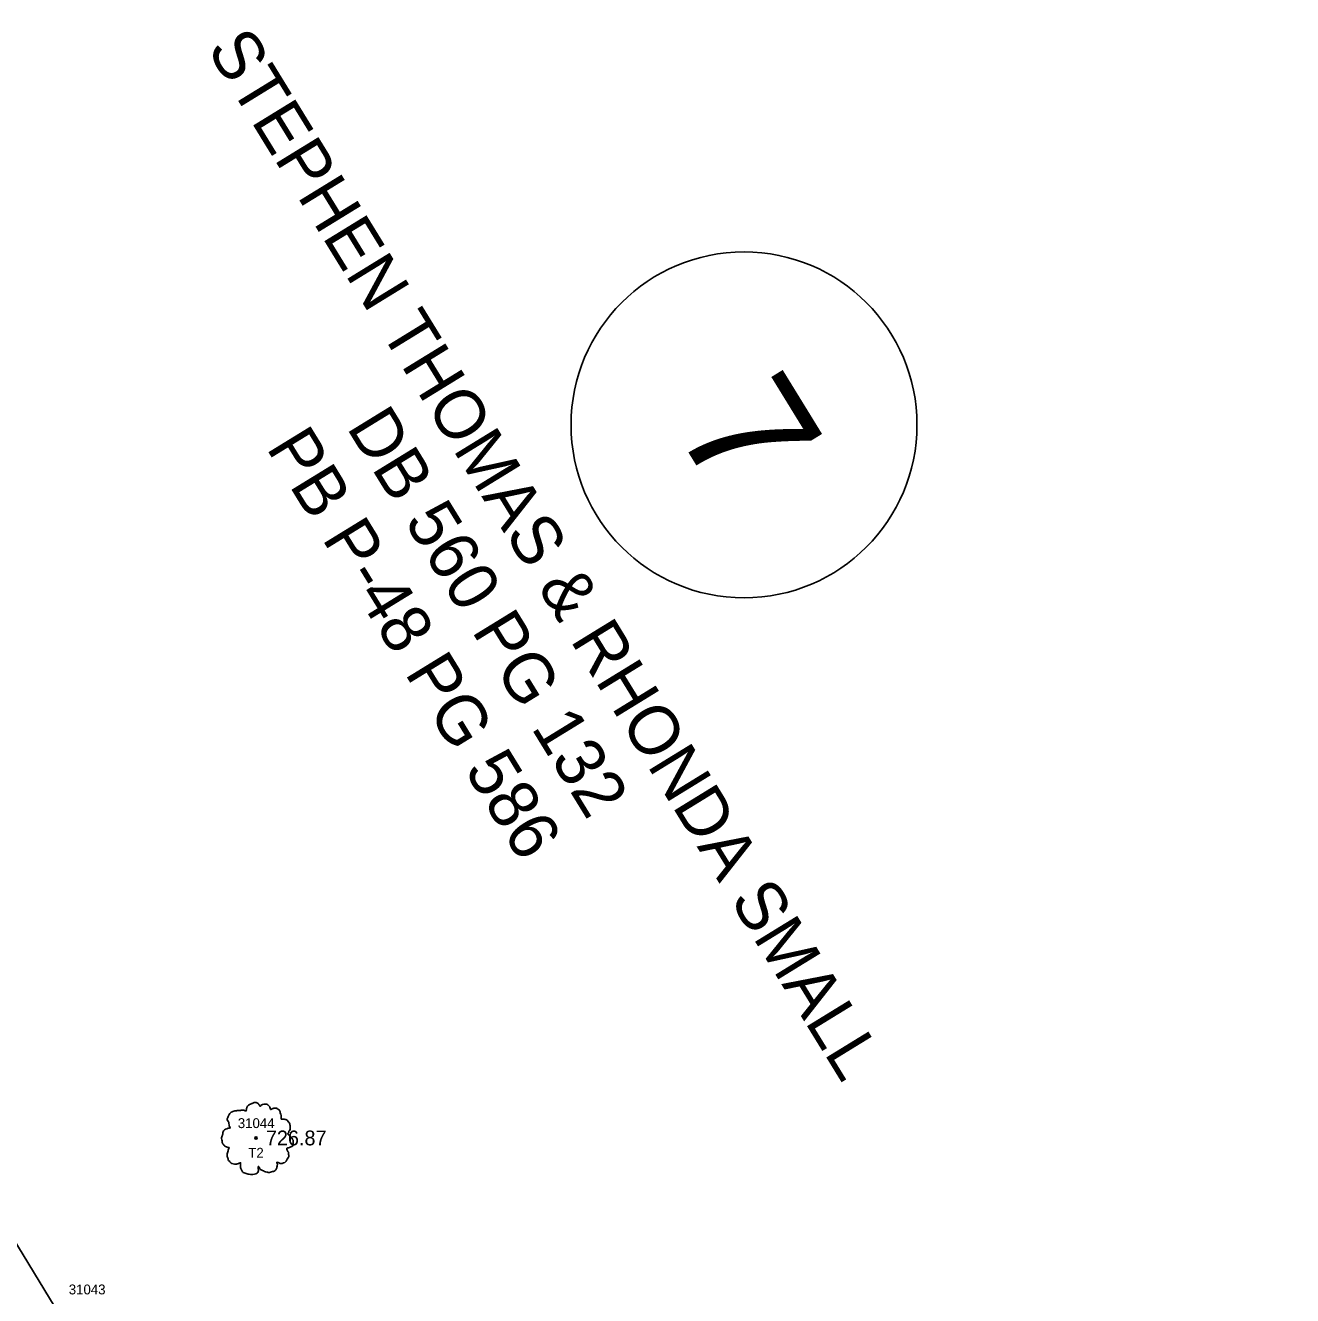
# Model space of a CAD drawing. Extents: x 1375131 to 1378678, y 999028 to 1004053.
# Drawn here: x 1377739.9 to 1377868.1, y 1001103.2 to 1001231.8 of the extents above; entities that cross this region are included whole.
import ezdxf

# ---------------------------------------------------------------- set-up
doc = ezdxf.new("R2010")
doc.units = 0
for name, color, linetype in [('RD_EX_DV_TX_Prop(Owner ID)', 7, 'Continuous'), ('RD_EX_Fence_Other_txCode', 7, 'Continuous'), ('RD_EX_RW', 7, 'Continuous'), ('RD_EX_TX_VEG_ELEV', 7, 'Continuous'), ('RD_EX_VEG', 7, 'Continuous'), ('RD_EX_VEG_txCode', 7, 'Continuous'), ('RD_SMD_Locator', 7, 'Continuous')]:
    doc.layers.add(name, color=color, linetype=linetype)

msp = doc.modelspace()

# ---------------------------------------------------------------- linework, layer by layer
at = {"layer": 'RD_EX_DV_TX_Prop(Owner ID)'}
msp.add_circle((1377812.64, 1001191.36), 17.5, dxfattribs=at)
at = {"layer": 'RD_EX_RW'}
msp.add_line((1377592.75, 1001348.44), (1377983.57, 1000707.36), dxfattribs=at)
at = {"layer": 'RD_EX_VEG'}
for centre, radius in [((1377763.27, 1001119.2), 0.125), ((1377763.26, 1001119.19), 0.00005)]:
    msp.add_circle(centre, radius, dxfattribs=at)
for points in [[(1377763.33, 1001122.78), (1377763.18, 1001122.8), (1377763.02, 1001122.75), (1377762.89, 1001122.7), (1377762.78, 1001122.66), (1377762.67, 1001122.61), (1377762.52, 1001122.52), (1377762.41, 1001122.42), (1377762.34, 1001122.3), (1377762.32, 1001122.18), (1377762.29, 1001122.05), (1377762.29, 1001121.96), (1377762.23, 1001121.95), (1377762.16, 1001121.96), (1377762.03, 1001122), (1377761.91, 1001122), (1377761.78, 1001122), (1377761.61, 1001121.98), (1377761.43, 1001121.98), (1377761.29, 1001121.96), (1377761.13, 1001121.93), (1377760.94, 1001121.87), (1377760.77, 1001121.81), (1377760.62, 1001121.68), (1377760.49, 1001121.45), (1377760.43, 1001121.27), (1377760.36, 1001121.15), (1377760.43, 1001120.92), (1377760.52, 1001120.75), (1377760.53, 1001120.65), (1377760.57, 1001120.43), (1377760.62, 1001120.32), (1377760.68, 1001120.22), (1377760.64, 1001120.21), (1377760.46, 1001120.18), (1377760.31, 1001120.13), (1377760.09, 1001120.02), (1377759.98, 1001119.91), (1377759.93, 1001119.75), (1377759.92, 1001119.57), (1377759.87, 1001119.47), (1377759.83, 1001119.33), (1377759.82, 1001119.3), (1377759.79, 1001119.13), (1377759.84, 1001118.91), (1377759.86, 1001118.73), (1377759.92, 1001118.62), (1377759.99, 1001118.53), (1377760.08, 1001118.41), (1377760.28, 1001118.3), (1377760.44, 1001118.25), (1377760.54, 1001118.23), (1377760.46, 1001117.98), (1377760.43, 1001117.81), (1377760.37, 1001117.61), (1377760.37, 1001117.57), (1377760.34, 1001117.34), (1377760.42, 1001117.17), (1377760.46, 1001116.99), (1377760.54, 1001116.87), (1377760.68, 1001116.72), (1377760.84, 1001116.61), (1377761.09, 1001116.55), (1377761.29, 1001116.56), (1377761.58, 1001116.65), (1377761.71, 1001116.69), (1377761.69, 1001116.6), (1377761.71, 1001116.41), (1377761.71, 1001116.2), (1377761.78, 1001116.04), (1377761.83, 1001115.9), (1377761.91, 1001115.77), (1377762.07, 1001115.66), (1377762.27, 1001115.62), (1377762.48, 1001115.55), (1377762.71, 1001115.51), (1377762.96, 1001115.5), (1377763.26, 1001115.57), (1377763.39, 1001115.64), (1377763.44, 1001115.72), (1377763.54, 1001115.91), (1377763.52, 1001116.02), (1377763.53, 1001116.32), (1377763.58, 1001116.24), (1377763.67, 1001116.06), (1377763.92, 1001115.91), (1377764.12, 1001115.82), (1377764.36, 1001115.75), (1377764.51, 1001115.71), (1377764.74, 1001115.75), (1377764.93, 1001115.79), (1377765.12, 1001115.85), (1377765.27, 1001115.99), (1377765.36, 1001116.12), (1377765.38, 1001116.26), (1377765.42, 1001116.45), (1377765.44, 1001116.54)], [(1377765.44, 1001116.54), (1377765.41, 1001116.62), (1377765.38, 1001116.75), (1377765.42, 1001116.74), (1377765.5, 1001116.71), (1377765.64, 1001116.65), (1377765.75, 1001116.61), (1377765.92, 1001116.62), (1377766.05, 1001116.67), (1377766.28, 1001116.81), (1377766.42, 1001117.05), (1377766.55, 1001117.25), (1377766.59, 1001117.41), (1377766.57, 1001117.52), (1377766.55, 1001117.77), (1377766.45, 1001117.9), (1377766.43, 1001117.96), (1377766.38, 1001118.16), (1377766.42, 1001118.18), (1377766.55, 1001118.21), (1377766.74, 1001118.27), (1377766.88, 1001118.33), (1377766.99, 1001118.42), (1377767.03, 1001118.53), (1377767.02, 1001118.73), (1377767.04, 1001118.93), (1377767, 1001119.01), (1377766.95, 1001119.08), (1377766.92, 1001119.18), (1377766.84, 1001119.26), (1377766.79, 1001119.33), (1377766.74, 1001119.38), (1377766.68, 1001119.46), (1377766.59, 1001119.52), (1377766.52, 1001119.55), (1377766.49, 1001119.62), (1377766.57, 1001119.72), (1377766.59, 1001119.77), (1377766.6, 1001119.88), (1377766.72, 1001120.06), (1377766.74, 1001120.26), (1377766.72, 1001120.47), (1377766.69, 1001120.61), (1377766.62, 1001120.75), (1377766.52, 1001120.87), (1377766.45, 1001120.96), (1377766.37, 1001121.02), (1377766.2, 1001121.08), (1377766.08, 1001121.11), (1377765.9, 1001121.11), (1377765.8, 1001121.13), (1377765.82, 1001121.16), (1377765.82, 1001121.23), (1377765.82, 1001121.37), (1377765.78, 1001121.6), (1377765.7, 1001121.85), (1377765.7, 1001121.86), (1377765.65, 1001121.98), (1377765.54, 1001122.08), (1377765.46, 1001122.13), (1377765.36, 1001122.2), (1377765.23, 1001122.21), (1377765.08, 1001122.21), (1377764.94, 1001122.18), (1377764.84, 1001122.13), (1377764.76, 1001122.07), (1377764.72, 1001122.15), (1377764.67, 1001122.3), (1377764.64, 1001122.37), (1377764.57, 1001122.46), (1377764.46, 1001122.56), (1377764.23, 1001122.62), (1377763.92, 1001122.58), (1377763.77, 1001122.48), (1377763.69, 1001122.4), (1377763.67, 1001122.46), (1377763.57, 1001122.56), (1377763.52, 1001122.65), (1377763.43, 1001122.71), (1377763.36, 1001122.76), (1377763.31, 1001122.78)]]:
    msp.add_spline(points, degree=3, dxfattribs=at)
at = {"layer": 'RD_SMD_Locator'}
msp.add_circle((1377763.27, 1001119.2), 0.075, dxfattribs=at)

# ---------------------------------------------------------------- texts
at = {"layer": 'RD_EX_DV_TX_Prop(Owner ID)'}
for s, height, p in [('STEPHEN THOMAS & RHONDA SMALL', 5, (1377758.23, 1001229.41)), ('7', 12.5, (1377805.46, 1001191.1)), ('DB 560 PG 132', 5, (1377772.37, 1001191.12)), ('PB P-48 PG 586', 5, (1377764.24, 1001189.06))]:
    msp.add_text(s, height=height, rotation=301.5778, dxfattribs=at).set_placement(p)
at = {"layer": 'RD_EX_Fence_Other_txCode'}
msp.add_text('31043', height=1, dxfattribs=at).set_placement((1377744.33, 1001103.37))
at = {"layer": 'RD_EX_TX_VEG_ELEV'}
msp.add_text('726.87', height=1.5, dxfattribs=at).set_placement((1377764.27, 1001118.45))
at = {"layer": 'RD_EX_VEG_txCode'}
for s, p in [('31044', (1377761.43, 1001120.2)), ('T2', (1377762.49, 1001117.2))]:
    msp.add_text(s, height=1, dxfattribs=at).set_placement(p)

doc.saveas('drawing.dxf')
